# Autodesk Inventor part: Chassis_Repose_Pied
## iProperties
Created: 2009-02
Part Number: Chassis_Repose_Pied
Document SubType Name: Sheet Metal
Designer: claivier
Author: claivier
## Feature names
1. Chanfrein de coin1
2. Perçage1 [Hole]
3. Perçage2 [Hole]
4. Miroir1 [Mirror]
5. Plaque1
6. Pli1
